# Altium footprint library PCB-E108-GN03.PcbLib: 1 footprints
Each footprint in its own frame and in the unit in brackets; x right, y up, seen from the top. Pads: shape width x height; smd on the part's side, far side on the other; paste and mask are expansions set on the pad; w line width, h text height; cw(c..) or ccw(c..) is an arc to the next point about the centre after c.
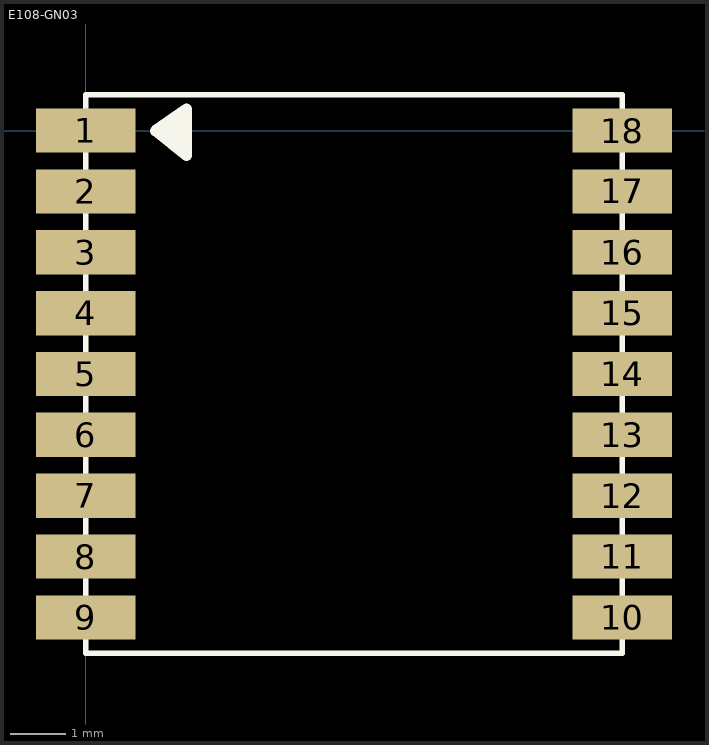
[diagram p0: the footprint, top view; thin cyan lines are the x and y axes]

## E108-GN03 [mm]
height 2.13
pads (18):
  rect 1.8x0.8 smd: 1(0,0) 2(0,-1.1) 3(0,-2.2) 4(0,-3.3) 5(0,-4.4) 6(0,-5.5) 7(0,-6.6) 8(0,-7.7) 9(0,-8.8) 10(9.7,-8.8) 11(9.7,-7.7) 12(9.7,-6.6) 13(9.7,-5.5) 14(9.7,-4.4) 15(9.7,-3.3) 16(9.7,-2.2) 17(9.7,-1.1) 18(9.7,0)
Top Overlay:
  region: 1.263,-0.005 1.635,-0.377 1.654,-0.396 1.697,-0.425 1.746,-0.445 1.797,-0.455 1.823,-0.455 1.823,0.389 1.784,0.389 1.706,0.373 1.633,0.343 1.567,0.299 1.539,0.271
  lines w0.1: 0,-9.45 9.7,-9.45 9.7,0.65 0,0.65 0,-9.45
  lines w0.2: 1.263,-0.005 1.823,-0.455 1.823,0.389 1.263,-0.005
